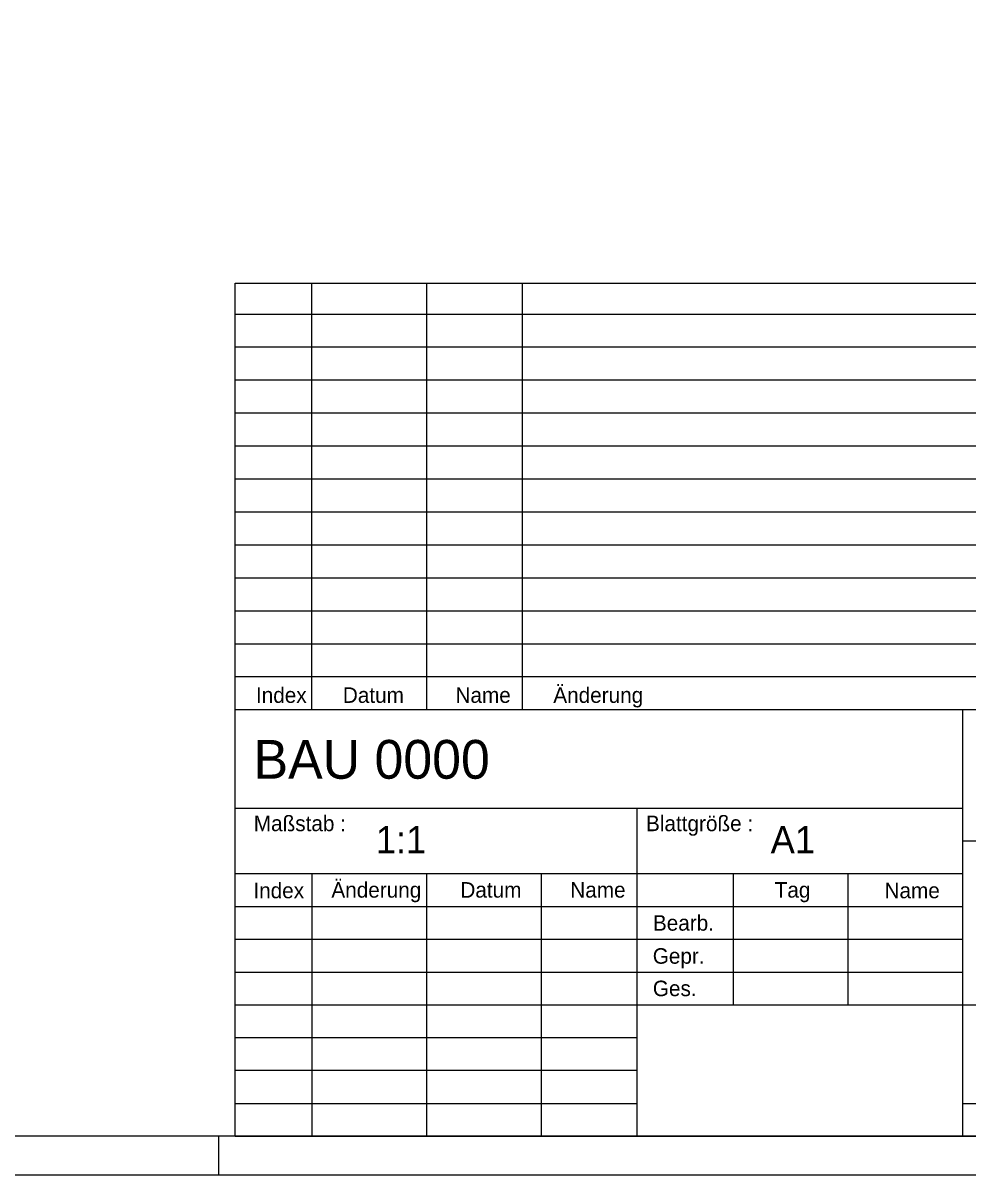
# Model space of a CAD drawing. Extents: x 0 to 841, y 0 to 594.
# Drawn here: x 630.8 to 752.7, y 0 to 148.5 of the extents above; entities that cross this region are included whole.
import ezdxf

# ---------------------------------------------------------------- set-up
doc = ezdxf.new("R2010")
doc.units = 0
doc.layers.add('90_Plankopf', color=7, linetype='Continuous')

msp = doc.modelspace()

# ---------------------------------------------------------------- linework, layer by layer
at = {"layer": '90_Plankopf'}
for p, q in [((658.12, 59.99), (658.12, 114.98)), ((658.12, 114.98), (836, 114.98)), ((668, 59.99), (668, 114.98)), ((682.83, 59.99), (682.83, 114.98)), ((695.18, 59.99), (695.18, 114.98)), ((658.12, 110.99), (836, 110.99)), ((658.12, 106.74), (836, 106.74)), ((658.12, 102.49), (836, 102.49)), ((658.12, 98.24), (836, 98.24)), ((658.12, 93.99), (836, 93.99)), ((658.12, 89.74), (836, 89.74)), ((658.12, 85.49), (836, 85.49)), ((658.12, 81.24), (836, 81.24)), ((658.12, 76.99), (836, 76.99)), ((658.12, 72.74), (836, 72.74)), ((658.12, 68.49), (836, 68.49)), ((658.12, 64.24), (836, 64.24)), ((658.12, 59.99), (836, 59.99)), ((658.12, 5), (658.12, 59.99)), ((658.12, 59.99), (836, 59.99)), ((752, 5), (752, 59.99)), ((658.12, 47.3), (752, 47.3)), ((710, 5), (710, 47.3)), ((752, 43.07), (836, 43.07)), ((658.12, 38.87), (752, 38.87)), ((668, 38.84), (668, 5)), ((682.83, 5), (682.83, 38.84)), ((697.65, 5), (697.65, 38.84)), ((722.35, 38.84), (722.35, 21.92)), ((737.18, 21.92), (737.18, 38.84)), ((658.12, 34.63), (752, 34.63)), ((658.12, 30.38), (752, 30.38)), ((658.12, 26.15), (752, 26.15)), ((658.12, 21.92), (752, 21.92)), ((658.12, 21.92), (752, 21.92)), ((710, 21.92), (752, 21.92)), ((752, 21.92), (836, 21.92)), ((710, 17.69), (658.12, 17.69)), ((710, 13.46), (658.12, 13.46)), ((658.12, 9.23), (710, 9.23)), ((752, 9.23), (836, 9.23)), ((656, 0), (656, 5)), ((836, 5), (658.12, 5)), ((658.12, 5), (710, 5)), ((669.8, 5), (836, 5)), ((669.8, 5), (836, 5))]:
    msp.add_line(p, q, dxfattribs=at)
for points in [[(0, 0), (841, 0), (841, 594), (0, 594)], [(25, 589), (836, 589), (836, 5), (25, 5)]]:
    msp.add_lwpolyline(points, close=True, dxfattribs=at)

# ---------------------------------------------------------------- texts
for s, height, p in [('Index', 2, (660.8, 60.86)), ('Datum', 2, (672.01, 60.86)), ('Name', 2, (686.54, 60.86)), ('Änderung', 2, (699.16, 60.86)), ('BAU 0000      ', 5, (660.49, 51.08)), ('Maßstab :', 2, (660.52, 44.32)), ('Blattgröße :', 1.9999, (711.12, 44.32)), ('1:1      ', 3.5, (676.26, 41.47)), ('A1       ', 3.5, (727.2, 41.47)), ('Index', 2, (660.47, 35.67)), ('Änderung', 2, (670.53, 35.75)), ('Datum', 2, (687.17, 35.75)), ('Name', 2, (701.35, 35.75)), ('Tag', 2, (727.72, 35.75)), ('Name', 2, (741.89, 35.67)), ('Bearb.', 2, (712.01, 31.49)), ('Gepr.', 2, (711.99, 27.23)), ('Ges.', 2, (712, 23.05))]:
    msp.add_text(s, height=height, dxfattribs=at).set_placement(p)

doc.saveas('drawing.dxf')
